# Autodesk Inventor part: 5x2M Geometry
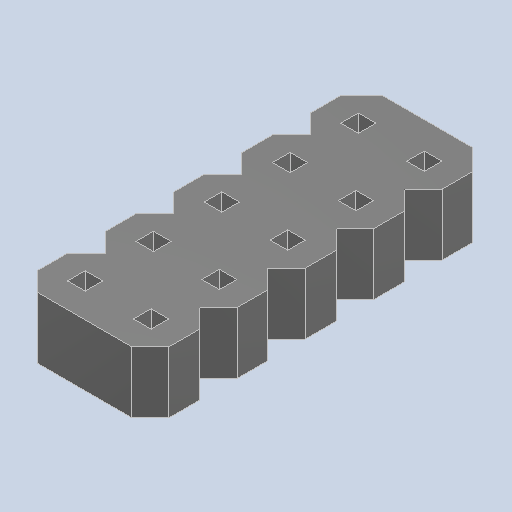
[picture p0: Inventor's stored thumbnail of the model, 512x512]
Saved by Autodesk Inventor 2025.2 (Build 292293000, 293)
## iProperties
Created: 2025-04
Part Number: 5x2M Geometry
Material: Generic
Description: PART-5x2M Geometry-DESC
Document SubType Name: Modeling
Designer: BennF
Density: 1 g/cm^3
Appearance: Default
Author: BennF
Revision Number: NONE
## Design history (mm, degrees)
feature "5"
body "Solid1"
